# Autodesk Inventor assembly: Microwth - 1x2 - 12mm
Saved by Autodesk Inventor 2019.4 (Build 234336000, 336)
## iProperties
Created: 2019-12
Part Number: Microwth - 1x2 - 12mm
Document SubType Name: Assembly
Designer: Administrator
Title: Microwth - 1x2 - 12mm v12
Author: Administrator
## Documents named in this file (10)
- c:\worker\convert-fusion-r09\tmp\job-1\3\output\files\e4c84826-0180-4e22-b740-8a53e6050974\afedd8f3-7a47-4895-a071-c7dbdd915689.iam
- c:\worker\convert-fusion-r09\tmp\job-1\3\output\files\e4c84826-0180-4e22-b740-8a53e6050974\Component1.ipt
- c:\worker\convert-fusion-r09\tmp\job-1\3\output\files\e4c84826-0180-4e22-b740-8a53e6050974\Component2.ipt
- c:\worker\convert-fusion-r09\tmp\job-1\3\output\files\e4c84826-0180-4e22-b740-8a53e6050974\Component3.ipt
- c:\worker\convert-fusion-r09\tmp\job-1\3\output\files\e4c84826-0180-4e22-b740-8a53e6050974\Component4.ipt
- c:\worker\convert-fusion-r09\tmp\job-1\3\output\files\e4c84826-0180-4e22-b740-8a53e6050974\Component5.ipt
- c:\worker\convert-fusion-r09\tmp\job-1\3\output\files\e4c84826-0180-4e22-b740-8a53e6050974\Component6.ipt
- c:\worker\convert-fusion-r09\tmp\job-1\3\output\files\e4c84826-0180-4e22-b740-8a53e6050974\Component7.ipt
- c:\worker\convert-fusion-r09\tmp\job-1\3\output\files\e4c84826-0180-4e22-b740-8a53e6050974\Pump v2.ipt
- c:\worker\convert-fusion-r09\tmp\job-1\3\output\files\e4c84826-0180-4e22-b740-8a53e6050974\Light assembly v3.iam
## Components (10 placed, 9 different names)
1. Component1:1
2. Component2:1
3. Component3:1
4. Component4:1
5. Component5:1
6. Component6:1
7. Component7:1
8. Component1:2
9. Pump v2:1
10. Light assembly v3:1 [sub-assembly]
